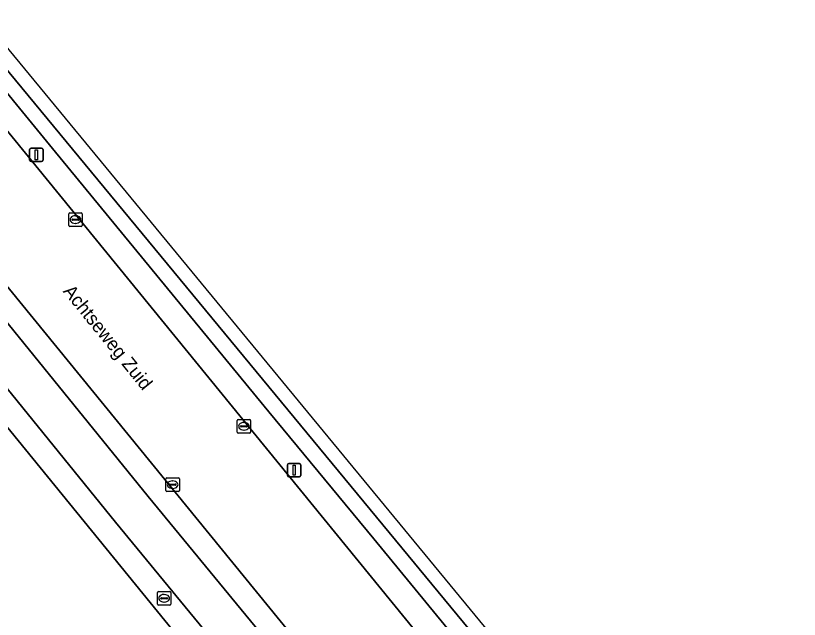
# Model space of a CAD drawing. Extents: x 157132 to 159279, y 384991 to 386650.
# Drawn here: x 158363.3 to 158421.5, y 386329.4 to 386374.1 of the extents above; entities that cross this region are included whole.
import ezdxf

# ---------------------------------------------------------------- set-up
doc = ezdxf.new("R2010")
doc.units = 0
for name, color, linetype in [('IMGEO_Berm_groen', 7, 'Continuous'), ('IMGEO_Fietspad_gesloten', 7, 'Continuous'), ('IMGEO_Gemengd_bos', 7, 'Continuous'), ('IMGEO_Grasland_overig', 7, 'Continuous'), ('IMGEO_Groenvoorziening', 7, 'Continuous'), ('IMGEO_Hek', 7, 'Continuous'), ('IMGEO_Kolk', 7, 'Continuous'), ('IMGEO_Lichtmast', 7, 'Continuous'), ('IMGEO_Openbare_ruimte_label', 7, 'Continuous'), ('IMGEO_Rijbaan_lokaal_open', 7, 'Continuous'), ('IMGEO_Rioolput', 7, 'Continuous'), ('IMGEO_Spoorbaan_halfverhard', 7, 'Continuous')]:
    doc.layers.add(name, color=color, linetype=linetype)

msp = doc.modelspace()

# ---------------------------------------------------------------- linework, layer by layer
at = {"layer": 'IMGEO_Berm_groen'}
msp.add_lwpolyline([(158321.486, 386416.081), (158427.029, 386286.802), (158427.217, 386286.955), (158427.331, 386287.448), (158427.408, 386287.512), (158427.22, 386289.38), (158427.45, 386289.573), (158423.35, 386294.581), (158412.264, 386308.098), (158389.899, 386335.322), (158382.122, 386344.736), (158366.306, 386364.001), (158359.943, 386371.744), (158320.294, 386419.889), (158310.741, 386431.42), (158304.43, 386439.057), (158293.115, 386452.371), (158288.318, 386457.955), (158285.542, 386455.743), (158285.345, 386455.586)], dxfattribs=at)
msp.add_lwpolyline([(158331.469, 386392.321), (158330.194, 386391.292), (158332.917, 386387.935), (158343.241, 386375.349), (158373.17, 386338.476), (158403.187, 386302.007), (158420.154, 386281.193), (158421.372, 386282.187)], close=True, dxfattribs=at)
at = {"layer": 'IMGEO_Fietspad_gesloten'}
msp.add_lwpolyline([(158311.106, 386409.764), (158316.532, 386403.284), (158324.083, 386393.968), (158330.416, 386386.328), (158340.811, 386373.482), (158370.754, 386336.554), (158400.841, 386299.998), (158408.202, 386290.97), (158414.262, 386283.538), (158417.764, 386279.242), (158420.154, 386281.193), (158403.187, 386302.007), (158373.17, 386338.476), (158343.241, 386375.349)], dxfattribs=at)
at = {"layer": 'IMGEO_Gemengd_bos'}
msp.add_lwpolyline([(158404.355, 386287.451), (158404.454, 386287.565), (158403.773, 386288.17), (158403.977, 386288.42), (158404.668, 386287.808), (158406.491, 386289.888), (158309.654, 386408.719)], dxfattribs=at)
at = {"layer": 'IMGEO_Grasland_overig'}
for points in [[(158320.294, 386419.889), (158359.943, 386371.744), (158366.306, 386364.001), (158382.122, 386344.736), (158389.899, 386335.322), (158412.264, 386308.098), (158423.35, 386294.581)], [(158423.503, 386296.229), (158408.781, 386314.342), (158346.523, 386389.687)]]:
    msp.add_lwpolyline(points, dxfattribs=at)
at = {"layer": 'IMGEO_Groenvoorziening'}
for points in [[(158340.811, 386373.482), (158330.416, 386386.328), (158324.083, 386393.968), (158316.532, 386403.284), (158311.106, 386409.764), (158310.087, 386409.251), (158309.654, 386408.719), (158406.491, 386289.888), (158407.049, 386289.203), (158408.305, 386287.662)], [(158408.202, 386290.97), (158400.841, 386299.998), (158370.754, 386336.554), (158340.811, 386373.482)]]:
    msp.add_lwpolyline(points, dxfattribs=at)
at = {"layer": 'IMGEO_Hek'}
msp.add_lwpolyline([(158423.35, 386294.581), (158412.264, 386308.098), (158389.899, 386335.322), (158382.122, 386344.736), (158366.306, 386364.001), (158359.943, 386371.744), (158320.294, 386419.889), (158310.741, 386431.42), (158304.43, 386439.057), (158293.115, 386452.371), (158288.318, 386457.955), (158283.695, 386463.336), (158282.157, 386461.93), (158278.128, 386466.274), (158276.042, 386467.327), (158272.251, 386467.953), (158267.264, 386469.128), (158267.021, 386469.184), (158263.452, 386473.157), (158261.818, 386475.083), (158252.208, 386486.509)], dxfattribs=at)
at = {"layer": 'IMGEO_Kolk'}
for p, q in [((158367.275, 386358.575), (158367.275, 386359.427)), ((158367.35, 386359.501), (158368.202, 386359.501)), ((158368.276, 386359.427), (158368.276, 386358.575)), ((158367.534, 386358.995), (158367.534, 386359.007)), ((158367.972, 386358.958), (158367.574, 386358.958)), ((158367.577, 386359.044), (158367.975, 386359.044)), ((158367.763, 386359.281), (158367.788, 386359.281)), ((158368.018, 386359.007), (158368.018, 386358.995)), ((158368.202, 386358.501), (158367.35, 386358.501)), ((158367.786, 386358.721), (158367.761, 386358.721)), ((158379.771, 386343.245), (158379.771, 386344.097)), ((158379.846, 386344.171), (158380.698, 386344.171)), ((158380.03, 386343.665), (158380.03, 386343.677)), ((158380.468, 386343.628), (158380.07, 386343.628)), ((158380.073, 386343.714), (158380.471, 386343.714)), ((158380.259, 386343.951), (158380.284, 386343.951)), ((158380.514, 386343.677), (158380.514, 386343.665)), ((158380.772, 386344.097), (158380.772, 386343.245)), ((158380.698, 386343.171), (158379.846, 386343.171)), ((158380.282, 386343.391), (158380.257, 386343.391)), ((158374.481, 386338.916), (158374.481, 386339.768)), ((158374.556, 386339.842), (158375.408, 386339.842)), ((158374.969, 386339.622), (158374.994, 386339.622)), ((158375.482, 386339.768), (158375.482, 386338.916)), ((158374.74, 386339.336), (158374.74, 386339.348)), ((158375.178, 386339.299), (158374.78, 386339.299)), ((158374.783, 386339.385), (158375.181, 386339.385)), ((158374.992, 386339.062), (158374.967, 386339.062)), ((158375.224, 386339.348), (158375.224, 386339.336)), ((158375.408, 386338.842), (158374.556, 386338.842))]:
    msp.add_line(p, q, dxfattribs=at)
for points in [[(158367.275, 386358.575), (158367.275, 386359.427)], [(158367.35, 386359.501), (158368.202, 386359.501)], [(158368.276, 386359.427), (158368.276, 386358.575)], [(158368.202, 386358.501), (158367.35, 386358.501)], [(158379.771, 386343.245), (158379.771, 386344.097)], [(158379.846, 386344.171), (158380.698, 386344.171)], [(158380.772, 386344.097), (158380.772, 386343.245)], [(158380.698, 386343.171), (158379.846, 386343.171)], [(158374.481, 386338.916), (158374.481, 386339.768)], [(158374.556, 386339.842), (158375.408, 386339.842)], [(158375.482, 386339.768), (158375.482, 386338.916)], [(158375.408, 386338.842), (158374.556, 386338.842)]]:
    msp.add_lwpolyline(points, dxfattribs=at)
for centre, radius, start, end in [((158367.352, 386359.425), 0.0765, 91.55205, 178.44795), ((158367.352, 386359.425), 0.0765, 91.55205, 178.44795), ((158368.2, 386359.425), 0.0765, 1.55205, 88.44795), ((158368.2, 386359.425), 0.0765, 1.55205, 88.44795), ((158367.574, 386359.004), 0.0403, 85.87752, 175.75265), ((158367.571, 386358.994), 0.0366, 178.93798, 274.71019), ((158367.975, 386359.001), 0.043, 264.86636, 352.45326), ((158367.979, 386359.006), 0.0386, 1.73085, 96.63898), ((158367.352, 386358.577), 0.0765, 181.55205, 268.44795), ((158367.352, 386358.577), 0.0765, 181.55205, 268.44795), ((158368.2, 386358.577), 0.0765, 271.55205, 358.44795), ((158368.2, 386358.577), 0.0765, 271.55205, 358.44795), ((158379.848, 386344.095), 0.0765, 91.55205, 178.44795), ((158379.848, 386344.095), 0.0765, 91.55205, 178.44795), ((158380.07, 386343.674), 0.0403, 85.87752, 175.75265), ((158380.067, 386343.664), 0.0366, 178.93798, 274.71019), ((158380.471, 386343.671), 0.043, 264.86636, 352.45326), ((158380.475, 386343.676), 0.0386, 1.73085, 96.63898), ((158380.696, 386344.095), 0.0765, 1.55205, 88.44795), ((158380.696, 386344.095), 0.0765, 1.55205, 88.44795), ((158379.848, 386343.247), 0.0765, 181.55205, 268.44795), ((158379.848, 386343.247), 0.0765, 181.55205, 268.44795), ((158380.696, 386343.247), 0.0765, 271.55205, 358.44795), ((158380.696, 386343.247), 0.0765, 271.55205, 358.44795), ((158374.558, 386339.766), 0.0765, 91.55205, 178.44795), ((158374.558, 386339.766), 0.0765, 91.55205, 178.44795), ((158375.406, 386339.766), 0.0765, 1.55205, 88.44795), ((158375.406, 386339.766), 0.0765, 1.55205, 88.44795), ((158374.78, 386339.345), 0.0403, 85.87752, 175.75265), ((158374.777, 386339.335), 0.0366, 178.93798, 274.71019), ((158375.181, 386339.342), 0.043, 264.86636, 352.45326), ((158375.185, 386339.347), 0.0386, 1.73085, 96.63898), ((158374.558, 386338.918), 0.0765, 181.55205, 268.44795), ((158374.558, 386338.918), 0.0765, 181.55205, 268.44795), ((158375.406, 386338.918), 0.0765, 271.55205, 358.44795), ((158375.406, 386338.918), 0.0765, 271.55205, 358.44795)]:
    msp.add_arc(centre, radius, start, end, dxfattribs=at)
for centre, major_axis, ratio, start_param, end_param in [((158367.762, 386359.001), (-0.387, 0.002), 0.722429, 4.712389, 7.853982), ((158367.787, 386359.001), (-0.39, 0.002), 0.717154, 1.570796, 4.712389), ((158380.258, 386343.671), (-0.387, 0.002), 0.722429, 4.712389, 7.853982), ((158380.283, 386343.671), (-0.39, 0.002), 0.717154, 1.570796, 4.712389), ((158374.968, 386339.342), (-0.387, 0.002), 0.722429, 4.712389, 7.853982), ((158374.993, 386339.342), (-0.39, 0.002), 0.717154, 1.570796, 4.712389)]:
    msp.add_ellipse(centre, major_axis=major_axis, ratio=ratio, start_param=start_param, end_param=end_param, dxfattribs=at)
at = {"layer": 'IMGEO_Lichtmast'}
for p, q in [((158364.378, 386363.411), (158364.378, 386364.211)), ((158364.378, 386364.211), (158364.378, 386363.411)), ((158364.478, 386364.311), (158365.268, 386364.311)), ((158365.268, 386364.311), (158364.478, 386364.311)), ((158365.368, 386364.211), (158365.368, 386363.411)), ((158365.368, 386363.411), (158365.368, 386364.211)), ((158365.268, 386363.311), (158364.478, 386363.311)), ((158364.478, 386363.311), (158365.268, 386363.311)), ((158383.495, 386340.023), (158383.495, 386340.823)), ((158383.495, 386340.823), (158383.495, 386340.023)), ((158383.595, 386340.923), (158384.385, 386340.923)), ((158384.385, 386340.923), (158383.595, 386340.923)), ((158384.485, 386340.823), (158384.485, 386340.023)), ((158384.485, 386340.023), (158384.485, 386340.823)), ((158384.385, 386339.923), (158383.595, 386339.923)), ((158383.595, 386339.923), (158384.385, 386339.923))]:
    msp.add_line(p, q, dxfattribs=at)
for points in [[(158364.798, 386364.186), (158364.948, 386364.186), (158364.948, 386363.436), (158364.798, 386363.436), (158364.798, 386364.186)], [(158383.915, 386340.798), (158384.065, 386340.798), (158384.065, 386340.048), (158383.915, 386340.048), (158383.915, 386340.798)]]:
    msp.add_lwpolyline(points, dxfattribs=at)
for centre, start, end in [((158364.478, 386364.211), 90, 180), ((158364.478, 386364.211), 90, 180), ((158365.268, 386364.211), 0, 90), ((158365.268, 386364.211), 360, 90), ((158364.478, 386363.411), 180, 270), ((158364.478, 386363.411), 180, 270), ((158365.268, 386363.411), 270, 0), ((158365.268, 386363.411), 270, 0), ((158383.595, 386340.823), 90, 180), ((158383.595, 386340.823), 90, 180), ((158384.385, 386340.823), 0, 90), ((158384.385, 386340.823), 360, 90), ((158383.595, 386340.023), 180, 270), ((158383.595, 386340.023), 180, 270), ((158384.385, 386340.023), 270, 0), ((158384.385, 386340.023), 270, 0)]:
    msp.add_arc(centre, 0.1, start, end, dxfattribs=at)
at = {"layer": 'IMGEO_Rijbaan_lokaal_open'}
msp.add_lwpolyline([(158321.486, 386416.081), (158315.843, 386411.463), (158326.303, 386398.649), (158331.469, 386392.321), (158421.372, 386282.187), (158427.029, 386286.802)], close=True, dxfattribs=at)
at = {"layer": 'IMGEO_Rioolput'}
for p, q in [((158373.93, 386331.413), (158374.782, 386331.413)), ((158373.855, 386330.487), (158373.855, 386331.339)), ((158374.114, 386330.907), (158374.114, 386330.919)), ((158374.552, 386330.87), (158374.154, 386330.87)), ((158374.157, 386330.956), (158374.555, 386330.956)), ((158374.343, 386331.193), (158374.368, 386331.193)), ((158374.598, 386330.919), (158374.598, 386330.907)), ((158374.856, 386331.339), (158374.856, 386330.487)), ((158374.782, 386330.413), (158373.93, 386330.413)), ((158374.366, 386330.633), (158374.341, 386330.633))]:
    msp.add_line(p, q, dxfattribs=at)
for points in [[(158373.93, 386331.413), (158374.782, 386331.413)], [(158373.855, 386330.487), (158373.855, 386331.339)], [(158374.856, 386331.339), (158374.856, 386330.487)], [(158374.782, 386330.413), (158373.93, 386330.413)]]:
    msp.add_lwpolyline(points, dxfattribs=at)
for centre, radius, start, end in [((158373.932, 386331.337), 0.0765, 91.55205, 178.44795), ((158373.932, 386331.337), 0.0765, 91.55205, 178.44795), ((158374.78, 386331.337), 0.0765, 1.55205, 88.44795), ((158374.78, 386331.337), 0.0765, 1.55205, 88.44795), ((158374.154, 386330.916), 0.0403, 85.87752, 175.75265), ((158374.151, 386330.906), 0.0366, 178.93798, 274.71019), ((158374.555, 386330.913), 0.043, 264.86636, 352.45326), ((158374.559, 386330.918), 0.0386, 1.73085, 96.63898), ((158373.932, 386330.489), 0.0765, 181.55205, 268.44795), ((158373.932, 386330.489), 0.0765, 181.55205, 268.44795), ((158374.78, 386330.489), 0.0765, 271.55205, 358.44795), ((158374.78, 386330.489), 0.0765, 271.55205, 358.44795)]:
    msp.add_arc(centre, radius, start, end, dxfattribs=at)
for centre, major_axis, ratio, start_param, end_param in [((158374.342, 386330.913), (-0.387, 0.002), 0.722429, 4.712389, 7.853982), ((158374.367, 386330.913), (-0.39, 0.002), 0.717154, 1.570796, 4.712389)]:
    msp.add_ellipse(centre, major_axis=major_axis, ratio=ratio, start_param=start_param, end_param=end_param, dxfattribs=at)
at = {"layer": 'IMGEO_Spoorbaan_halfverhard'}
msp.add_lwpolyline([(158466.92, 386245.385), (158362.518, 386372.019), (158294.663, 386454.387), (158291.256, 386458.523), (158262.301, 386493.642), (158261.201, 386492.741), (158283.609, 386465.705), (158298.814, 386447.192), (158346.523, 386389.687), (158408.781, 386314.342), (158423.503, 386296.229)], dxfattribs=at)

# ---------------------------------------------------------------- texts
at = {"layer": 'IMGEO_Openbare_ruimte_label'}
msp.add_text('Achtseweg Zuid', height=1, rotation=308.95496, dxfattribs=at).set_placement((158366.806, 386353.668))

doc.saveas('drawing.dxf')
